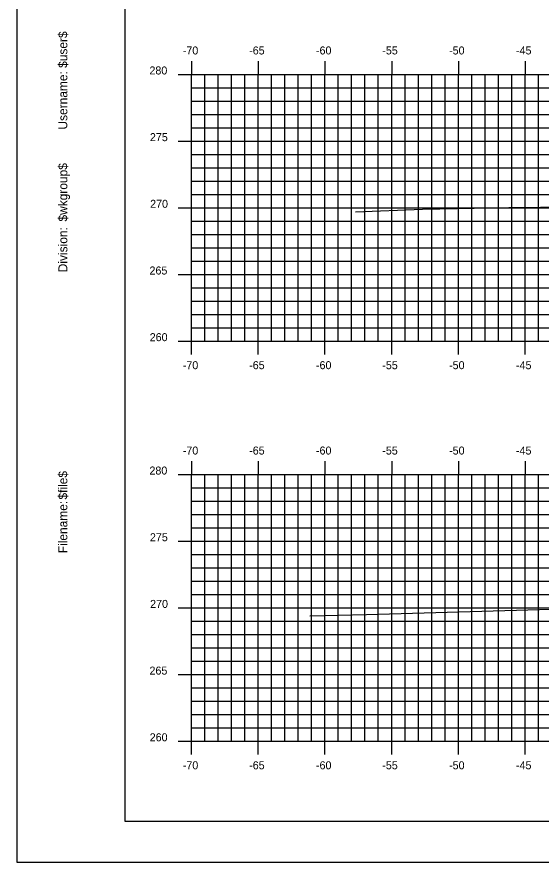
# Model space of a CAD drawing. Extents: x 854899 to 855069, y 366268 to 366378.
# Drawn here: x 854898.7 to 854938, y 366268.2 to 366331.6 of the extents above; entities that cross this region are included whole.
import ezdxf

# ---------------------------------------------------------------- set-up
doc = ezdxf.new("R2010")
doc.units = 0
for name, color, linetype in [('BORDER', 7, 'Continuous'), ('H_V ANNOTATION', 7, 'Continuous'), ('MAJOR', 7, 'Continuous'), ('MINOR', 7, 'Continuous'), ('PLOT BOUNDARY', 7, 'Continuous'), ('S_Roadway_Centerline', 7, 'Continuous')]:
    doc.layers.add(name, color=color, linetype=linetype)

msp = doc.modelspace()

# ---------------------------------------------------------------- linework, layer by layer
at = {"layer": 'BORDER'}
for p, q in [((854906.774, 366376.236), (854906.774, 366271.236)), ((854906.774, 366271.236), (855066.774, 366271.236))]:
    msp.add_line(p, q, dxfattribs=at)
at = {"layer": 'MAJOR'}
for p, q in [((854911.774, 366328.238), (854911.774, 366327.236)), ((854916.774, 366328.238), (854916.774, 366327.236)), ((854921.774, 366328.238), (854921.774, 366327.236)), ((854926.774, 366328.238), (854926.774, 366327.236)), ((854931.774, 366328.238), (854931.774, 366327.236)), ((854936.774, 366328.238), (854936.774, 366327.236)), ((854910.772, 366327.236), (854911.774, 366327.236)), ((854911.774, 366327.236), (855051.774, 366327.236)), ((854911.774, 366307.236), (854911.774, 366327.236)), ((854911.774, 366307.236), (854911.774, 366327.236)), ((854911.774, 366327.236), (855051.774, 366327.236)), ((854916.774, 366307.236), (854916.774, 366327.236)), ((854921.774, 366307.236), (854921.774, 366327.236)), ((854926.774, 366307.236), (854926.774, 366327.236)), ((854931.774, 366307.236), (854931.774, 366327.236)), ((854936.774, 366307.236), (854936.774, 366327.236)), ((854910.772, 366322.236), (854911.774, 366322.236)), ((854911.774, 366322.236), (855051.774, 366322.236)), ((854910.772, 366317.236), (854911.774, 366317.236)), ((854911.774, 366317.236), (855051.774, 366317.236)), ((854910.772, 366312.236), (854911.774, 366312.236)), ((854911.774, 366312.236), (855051.774, 366312.236)), ((854910.772, 366307.236), (854911.774, 366307.236)), ((854911.774, 366307.236), (855051.774, 366307.236)), ((854911.774, 366307.236), (855051.774, 366307.236)), ((854911.774, 366306.234), (854911.774, 366307.236)), ((854916.774, 366306.234), (854916.774, 366307.236)), ((854921.774, 366306.234), (854921.774, 366307.236)), ((854926.774, 366306.234), (854926.774, 366307.236)), ((854931.774, 366306.234), (854931.774, 366307.236)), ((854936.774, 366306.234), (854936.774, 366307.236)), ((854911.774, 366298.238), (854911.774, 366297.236)), ((854916.774, 366298.238), (854916.774, 366297.236)), ((854921.774, 366298.238), (854921.774, 366297.236)), ((854926.774, 366298.238), (854926.774, 366297.236)), ((854931.774, 366298.238), (854931.774, 366297.236)), ((854936.774, 366298.238), (854936.774, 366297.236)), ((854910.772, 366297.236), (854911.774, 366297.236)), ((854911.774, 366297.236), (855051.774, 366297.236)), ((854911.774, 366277.236), (854911.774, 366297.236)), ((854911.774, 366277.236), (854911.774, 366297.236)), ((854911.774, 366297.236), (855051.774, 366297.236)), ((854916.774, 366277.236), (854916.774, 366297.236)), ((854921.774, 366277.236), (854921.774, 366297.236)), ((854926.774, 366277.236), (854926.774, 366297.236)), ((854931.774, 366277.236), (854931.774, 366297.236)), ((854936.774, 366277.236), (854936.774, 366297.236)), ((854910.772, 366292.236), (854911.774, 366292.236)), ((854911.774, 366292.236), (855051.774, 366292.236)), ((854910.772, 366287.236), (854911.774, 366287.236)), ((854911.774, 366287.236), (855051.774, 366287.236)), ((854910.772, 366282.236), (854911.774, 366282.236)), ((854911.774, 366282.236), (855051.774, 366282.236)), ((854910.772, 366277.236), (854911.774, 366277.236)), ((854911.774, 366277.236), (855051.774, 366277.236)), ((854911.774, 366277.236), (855051.774, 366277.236)), ((854911.774, 366276.234), (854911.774, 366277.236)), ((854916.774, 366276.234), (854916.774, 366277.236)), ((854921.774, 366276.234), (854921.774, 366277.236)), ((854926.774, 366276.234), (854926.774, 366277.236)), ((854931.774, 366276.234), (854931.774, 366277.236)), ((854936.774, 366276.234), (854936.774, 366277.236))]:
    msp.add_line(p, q, dxfattribs=at)
at = {"layer": 'MINOR'}
for p, q in [((854912.774, 366307.236), (854912.774, 366327.236)), ((854913.774, 366307.236), (854913.774, 366327.236)), ((854914.774, 366307.236), (854914.774, 366327.236)), ((854915.774, 366307.236), (854915.774, 366327.236)), ((854917.774, 366307.236), (854917.774, 366327.236)), ((854918.774, 366307.236), (854918.774, 366327.236)), ((854919.774, 366307.236), (854919.774, 366327.236)), ((854920.774, 366307.236), (854920.774, 366327.236)), ((854922.774, 366307.236), (854922.774, 366327.236)), ((854923.774, 366307.236), (854923.774, 366327.236)), ((854924.774, 366307.236), (854924.774, 366327.236)), ((854925.774, 366307.236), (854925.774, 366327.236)), ((854927.774, 366307.236), (854927.774, 366327.236)), ((854928.774, 366307.236), (854928.774, 366327.236)), ((854929.774, 366307.236), (854929.774, 366327.236)), ((854930.774, 366307.236), (854930.774, 366327.236)), ((854932.774, 366307.236), (854932.774, 366327.236)), ((854933.774, 366307.236), (854933.774, 366327.236)), ((854934.774, 366307.236), (854934.774, 366327.236)), ((854935.774, 366307.236), (854935.774, 366327.236)), ((854937.774, 366307.236), (854937.774, 366327.236)), ((854911.774, 366326.236), (855051.774, 366326.236)), ((854911.774, 366326.236), (854912.776, 366326.236)), ((854911.774, 366325.236), (855051.774, 366325.236)), ((854911.774, 366325.236), (854912.776, 366325.236)), ((854911.774, 366324.236), (855051.774, 366324.236)), ((854911.774, 366324.236), (854912.776, 366324.236)), ((854911.774, 366323.236), (855051.774, 366323.236)), ((854911.774, 366323.236), (854912.776, 366323.236)), ((854911.774, 366321.236), (855051.774, 366321.236)), ((854911.774, 366321.236), (854912.776, 366321.236)), ((854911.774, 366320.236), (855051.774, 366320.236)), ((854911.774, 366320.236), (854912.776, 366320.236)), ((854911.774, 366319.236), (855051.774, 366319.236)), ((854911.774, 366319.236), (854912.776, 366319.236)), ((854911.774, 366318.236), (855051.774, 366318.236)), ((854911.774, 366318.236), (854912.776, 366318.236)), ((854911.774, 366316.236), (855051.774, 366316.236)), ((854911.774, 366316.236), (854912.776, 366316.236)), ((854911.774, 366315.236), (855051.774, 366315.236)), ((854911.774, 366315.236), (854912.776, 366315.236)), ((854911.774, 366314.236), (855051.774, 366314.236)), ((854911.774, 366314.236), (854912.776, 366314.236)), ((854911.774, 366313.236), (855051.774, 366313.236)), ((854911.774, 366313.236), (854912.776, 366313.236)), ((854911.774, 366311.236), (854912.776, 366311.236)), ((854911.774, 366311.236), (855051.774, 366311.236)), ((854911.774, 366310.236), (855051.774, 366310.236)), ((854911.774, 366310.236), (854912.776, 366310.236)), ((854911.774, 366309.236), (855051.774, 366309.236)), ((854911.774, 366309.236), (854912.776, 366309.236)), ((854911.774, 366308.236), (855051.774, 366308.236)), ((854911.774, 366308.236), (854912.776, 366308.236)), ((854911.774, 366277.236), (854911.774, 366297.236)), ((854912.774, 366277.236), (854912.774, 366297.236)), ((854913.774, 366277.236), (854913.774, 366297.236)), ((854914.774, 366277.236), (854914.774, 366297.236)), ((854915.774, 366277.236), (854915.774, 366297.236)), ((854917.774, 366277.236), (854917.774, 366297.236)), ((854918.774, 366277.236), (854918.774, 366297.236)), ((854919.774, 366277.236), (854919.774, 366297.236)), ((854920.774, 366277.236), (854920.774, 366297.236)), ((854922.774, 366277.236), (854922.774, 366297.236)), ((854923.774, 366277.236), (854923.774, 366297.236)), ((854924.774, 366277.236), (854924.774, 366297.236)), ((854925.774, 366277.236), (854925.774, 366297.236)), ((854927.774, 366277.236), (854927.774, 366297.236)), ((854928.774, 366277.236), (854928.774, 366297.236)), ((854929.774, 366277.236), (854929.774, 366297.236)), ((854930.774, 366277.236), (854930.774, 366297.236)), ((854932.774, 366277.236), (854932.774, 366297.236)), ((854933.774, 366277.236), (854933.774, 366297.236)), ((854934.774, 366277.236), (854934.774, 366297.236)), ((854935.774, 366277.236), (854935.774, 366297.236)), ((854937.774, 366277.236), (854937.774, 366297.236)), ((854911.774, 366296.236), (855051.774, 366296.236)), ((854911.774, 366296.236), (854912.776, 366296.236)), ((854911.774, 366295.236), (855051.774, 366295.236)), ((854911.774, 366295.236), (854912.776, 366295.236)), ((854911.774, 366294.236), (855051.774, 366294.236)), ((854911.774, 366294.236), (854912.776, 366294.236)), ((854911.774, 366293.236), (855051.774, 366293.236)), ((854911.774, 366293.236), (854912.776, 366293.236)), ((854911.774, 366291.236), (855051.774, 366291.236)), ((854911.774, 366291.236), (854912.776, 366291.236)), ((854911.774, 366290.236), (855051.774, 366290.236)), ((854911.774, 366290.236), (854912.776, 366290.236)), ((854911.774, 366289.236), (855051.774, 366289.236)), ((854911.774, 366289.236), (854912.776, 366289.236)), ((854911.774, 366288.236), (855051.774, 366288.236)), ((854911.774, 366288.236), (854912.776, 366288.236)), ((854911.774, 366286.236), (855051.774, 366286.236)), ((854911.774, 366286.236), (854912.776, 366286.236)), ((854911.774, 366285.236), (855051.774, 366285.236)), ((854911.774, 366285.236), (854912.776, 366285.236)), ((854911.774, 366284.236), (855051.774, 366284.236)), ((854911.774, 366284.236), (854912.776, 366284.236)), ((854911.774, 366283.236), (855051.774, 366283.236)), ((854911.774, 366283.236), (854912.776, 366283.236)), ((854911.774, 366281.236), (855051.774, 366281.236)), ((854911.774, 366281.236), (854912.776, 366281.236)), ((854911.774, 366280.236), (855051.774, 366280.236)), ((854911.774, 366280.236), (854912.776, 366280.236)), ((854911.774, 366279.236), (855051.774, 366279.236)), ((854911.774, 366279.236), (854912.776, 366279.236)), ((854911.774, 366278.236), (855051.774, 366278.236)), ((854911.774, 366278.236), (854912.776, 366278.236))]:
    msp.add_line(p, q, dxfattribs=at)
at = {"layer": 'PLOT BOUNDARY'}
msp.add_lwpolyline([(854898.681, 366268.177), (855068.681, 366268.177), (855068.681, 366378.177), (854898.681, 366378.177)], close=True, dxfattribs=at)
at = {"layer": 'S_Roadway_Centerline'}
for points in [[(854924.068, 366316.94), (854929.097, 366317.144), (854935.552, 366317.258), (854949.789, 366317.41), (854960.814, 366317.707), (854961.589, 366317.66), (854964.403, 366317.388), (854965.385, 366317.346), (854970.188, 366317.674), (854971.488, 366317.76), (854972.612, 366317.778), (854982.41, 366318.199), (854987.873, 366318.081), (854993.388, 366318.007), (854995.003, 366317.976), (854999.964, 366317.964), (855001.001, 366318.016), (855005.553, 366318.042), (855007.414, 366318.074), (855018.059, 366317.982)], [(854920.631, 366286.642), (854924.888, 366286.755), (854939.58, 366287.166), (854945.963, 366287.37), (854957.486, 366287.942), (854961.059, 366288.051), (854961.286, 366288.106), (854963.414, 366288.013), (854965.316, 366287.948), (854966.506, 366288), (854971.338, 366288.32), (854977.246, 366288.416), (854982.457, 366288.64), (854989.068, 366288.497), (854993.573, 366288.403), (854996.105, 366288.282), (854996.433, 366288.257), (854999.77, 366288.409), (854999.893, 366288.419), (855006.72, 366288.819), (855009.438, 366288.75)]]:
    msp.add_lwpolyline(points, dxfattribs=at)

# ---------------------------------------------------------------- texts
at = {"layer": 'BORDER'}
for s, p in [('$user$', (854902.459, 366327.728)), ('Username:', (854902.459, 366323.104)), ('$wkgroup$', (854902.459, 366316.206)), ('Division:', (854902.459, 366312.403)), ('$file$', (854902.459, 366295.362)), ('Filename:', (854902.459, 366291.335))]:
    msp.add_text(s, height=0.6696, rotation=90, dxfattribs=at).set_placement(p)
at = {"layer": 'H_V ANNOTATION'}
for s, p in [('-70', (854911.116, 366328.736)), ('-65', (854916.092, 366328.736)), ('-60', (854921.1, 366328.736)), ('-55', (854926.07, 366328.736)), ('-50', (854931.078, 366328.736)), ('-45', (854936.092, 366328.736)), ('280', (854908.615, 366327.236)), ('275', (854908.652, 366322.236)), ('270', (854908.668, 366317.236)), ('265', (854908.62, 366312.236)), ('260', (854908.636, 366307.236)), ('-70', (854911.116, 366305.136)), ('-65', (854916.092, 366305.136)), ('-60', (854921.1, 366305.136)), ('-55', (854926.07, 366305.136)), ('-50', (854931.078, 366305.136)), ('-45', (854936.092, 366305.136)), ('-70', (854911.116, 366298.736)), ('-65', (854916.092, 366298.736)), ('-60', (854921.1, 366298.736)), ('-55', (854926.07, 366298.736)), ('-50', (854931.078, 366298.736)), ('-45', (854936.092, 366298.736)), ('280', (854908.615, 366297.236)), ('275', (854908.652, 366292.236)), ('270', (854908.668, 366287.236)), ('265', (854908.62, 366282.236)), ('260', (854908.636, 366277.236)), ('-70', (854911.116, 366275.136)), ('-65', (854916.092, 366275.136)), ('-60', (854921.1, 366275.136)), ('-55', (854926.07, 366275.136)), ('-50', (854931.078, 366275.136)), ('-45', (854936.092, 366275.136))]:
    msp.add_text(s, height=0.6, dxfattribs=at).set_placement(p)

doc.saveas('drawing.dxf')
